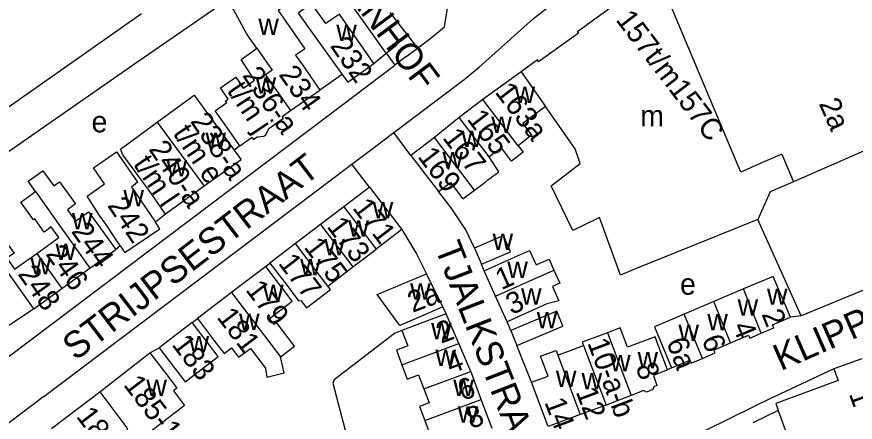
# Model space of a CAD drawing. Extents: x 159261 to 160849, y 382514 to 384534.
# Drawn here: x 159434.5 to 159592.3, y 383430.4 to 383506.6 of the extents above; entities that cross this region are included whole.
import ezdxf

# ---------------------------------------------------------------- set-up
doc = ezdxf.new("R2010")
doc.units = 0
for name, color, linetype in [('BLT_Basislijn', 7, 'Continuous'), ('BLT_Bebouwing', 7, 'Continuous'), ('BLT_Centroide', 7, 'Continuous'), ('BLT_Huisnummer', 7, 'Continuous'), ('BLT_Huisnummer_ tussenligend', 7, 'Continuous'), ('BLT_Huisnummer_reeks', 7, 'Continuous'), ('BLT_Onderverdeling_panden', 7, 'Continuous'), ('BLT_Straatnaam', 7, 'Continuous'), ('BLT_Vlakafsluiter', 7, 'Continuous')]:
    doc.layers.add(name, color=color, linetype=linetype)

msp = doc.modelspace()

# ---------------------------------------------------------------- linework, layer by layer
at = {"layer": 'BLT_Basislijn'}
for p, q in [((159504.04, 383499.76), (159490.29, 383519.05)), ((159474.26, 383509.88), (159456.51, 383497.57)), ((159504.7, 383507.46), (159509.94, 383500.74)), ((159504.04, 383499.76), (159506.03, 383501.34)), ((159501.7, 383497.84), (159504.04, 383499.76)), ((159504.04, 383499.76), (159505.65, 383497.5)), ((159456.51, 383497.57), (159422.23, 383473.79)), ((159495.77, 383495.76), (159491.55, 383492.84)), ((159508.68, 383480.51), (159505.5, 383484.86)), ((159476.46, 383482.36), (159475.45, 383481.51)), ((159500.88, 383474.55), (159497.57, 383478.88)), ((159462.52, 383469.49), (159460.59, 383467.98)), ((159582.13, 383450.36), (159573.98, 383468.47)), ((159454, 383463.51), (159453.14, 383462.88)), ((159481.37, 383459.66), (159482.14, 383460.29)), ((159522.47, 383458.85), (159521.96, 383460.08)), ((159515.33, 383450.76), (159514.66, 383452.08)), ((159467.55, 383449.1), (159468.52, 383449.86)), ((159582.13, 383450.36), (159580.11, 383450.13)), ((159527.46, 383447.6), (159526.77, 383449.24)), ((159459.55, 383443.43), (159461.32, 383444.35)), ((159531.39, 383437.88), (159528.62, 383444.82)), ((159557.75, 383440.56), (159556.95, 383440.24)), ((159577.81, 383432.59), (159573.03, 383430.24))]:
    msp.add_line(p, q, dxfattribs=at)
for points in [[(159505.5, 383484.86), (159518.69, 383494.81), (159521.53, 383497.18), (159531.74, 383506.29), (159551.48, 383521.62), (159560.64, 383527.81), (159570.61, 383533.89), (159574.46, 383535.84), (159576.68, 383536.75), (159577.57, 383534.45), (159623.26, 383552.14), (159622.41, 383554.33), (159627.34, 383556.21), (159628.86, 383556.59), (159630.56, 383556.59), (159632, 383556.22), (159633.7, 383555.46), (159634.34, 383554.89), (159634.81, 383554.05)], [(159509.94, 383500.74), (159512.47, 383502.65), (159515, 383504.75), (159515.83, 383509.77), (159535.19, 383525.66), (159540.37, 383529.61), (159549.52, 383536.01), (159553.92, 383535.43), (159554.55, 383535.97), (159555.34, 383537.11), (159555.78, 383538.15), (159555.95, 383539.22), (159555.84, 383540.38), (159555.5, 383541.77)], [(159422.23, 383473.79), (159418.8, 383478.76), (159418.9, 383479.86), (159458, 383507.23)], [(159507.74, 383499.08), (159509.94, 383500.74)], [(159430.35, 383440.97), (159433.6, 383443.17), (159492.79, 383487.8), (159505.65, 383497.5)], [(159497.57, 383478.88), (159501.56, 383481.89)], [(159439.63, 383435.19), (159497.57, 383478.88)], [(159520.66, 383463.11), (159519.02, 383466.54), (159516.28, 383470.69), (159513.89, 383473.73)], [(159628.07, 383468.9), (159621.56, 383466.62), (159582.13, 383450.36)], [(159506.95, 383466.59), (159509.72, 383462.03), (159511.6, 383458.28)], [(159437.72, 383451.68), (159432.56, 383448.25), (159426.76, 383444.96), (159420.88, 383442.27), (159412.54, 383439.19), (159400.66, 383435.2)], [(159507, 383447.64), (159505.57, 383447.05), (159494.22, 383438.3), (159494.02, 383437.69), (159498.26, 383421.44)], [(159588.26, 383440.37), (159576.24, 383434.73), (159573.02, 383433.17), (159555.06, 383424.37), (159552.31, 383421.68), (159551.85, 383417.92), (159572.25, 383356.82)], [(159439.63, 383435.19), (159399.52, 383404.89)]]:
    msp.add_lwpolyline(points, dxfattribs=at)
at = {"layer": 'BLT_Bebouwing'}
for p, q in [((159543.32, 383506.24), (159551.33, 383512.07)), ((159532.72, 383498.22), (159540.25, 383503.62)), ((159529.42, 383496.29), (159522.24, 383491.08)), ((159486.05, 383488.98), (159491.55, 383492.84)), ((159522.24, 383491.08), (159517.79, 383487.68)), ((159517.79, 383487.68), (159513.14, 383483.89)), ((159603.64, 383485.66), (159580.7, 383475.6)), ((159513.14, 383483.89), (159508.68, 383480.51)), ((159508.68, 383480.51), (159513.89, 383473.73)), ((159469.79, 383474.74), (159462.52, 383469.49)), ((159500.88, 383474.55), (159506.95, 383466.59)), ((159496.05, 383470.9), (159491.69, 383467.57)), ((159491.69, 383467.57), (159486.96, 383463.96)), ((159486.96, 383463.96), (159482.14, 383460.29)), ((159448.29, 383459.36), (159453.14, 383462.88)), ((159520.66, 383463.11), (159521.96, 383460.08)), ((159442.98, 383455.5), (159448.29, 383459.36)), ((159481.37, 383459.66), (159474.95, 383454.76)), ((159493.05, 383455.98), (159497.77, 383459.59)), ((159514.66, 383452.08), (159511.6, 383458.28)), ((159524.62, 383454.05), (159522.47, 383458.85)), ((159437.72, 383451.68), (159442.98, 383455.5)), ((159474.95, 383454.76), (159468.52, 383449.86)), ((159571.26, 383455.42), (159565.68, 383453.04)), ((159526.77, 383449.24), (159524.62, 383454.05)), ((159565.68, 383453.04), (159560.11, 383450.66)), ((159517.69, 383445.18), (159515.33, 383450.76)), ((159467.55, 383449.1), (159461.32, 383444.35)), ((159527.46, 383447.6), (159528.62, 383444.82)), ((159519.93, 383439.92), (159517.69, 383445.18)), ((159450.14, 383436.07), (159459.55, 383443.43)), ((159536.34, 383442.94), (159541.18, 383444.76)), ((159593.52, 383442.31), (159588.26, 383440.37)), ((159441.02, 383429.18), (159450.14, 383436.07)), ((159523.97, 383429.19), (159521.93, 383434.65)), ((159550.15, 383435.39), (159545.4, 383433.59)), ((159577.34, 383433.88), (159577.81, 383432.59)), ((159545.4, 383433.59), (159540.54, 383431.78)), ((159577.81, 383432.59), (159584.04, 383415.32))]:
    msp.add_line(p, q, dxfattribs=at)
for points in [[(159479.51, 383514.59), (159479.76, 383514.15), (159482.73, 383516.23), (159486.55, 383508.99), (159485.26, 383508.1), (159484.96, 383508.66), (159483.73, 383507.8), (159488.7, 383500.6), (159487.86, 383500), (159486.99, 383499.4), (159488.7, 383496.95), (159491.55, 383492.84)], [(159479.71, 383500.7), (159478.13, 383502.94), (159477.71, 383503.62), (159475.33, 383507.97), (159474.26, 383509.88)], [(159501.7, 383497.84), (159495.23, 383507.14), (159492.65, 383505.34), (159489.95, 383509.11), (159487.48, 383507.34), (159495.77, 383495.76)], [(159540.25, 383503.62), (159540.06, 383503.89), (159543.32, 383506.24)], [(159476.46, 383482.36), (159473.59, 383486.46), (159471.84, 383488.96), (159474.02, 383490.49), (159473.81, 383490.8), (159474.31, 383491.16), (159472.86, 383493.24), (159475.73, 383495.25), (159477.15, 383493.23), (159479.24, 383494.69), (159476.72, 383498.61), (159478.71, 383500), (159479.71, 383500.7)], [(159495.77, 383495.76), (159496.81, 383494.3), (159501.7, 383497.84)], [(159532.72, 383498.22), (159532.52, 383498.5), (159529.42, 383496.29)], [(159460.94, 383486.78), (159467.89, 383491.89), (159475.45, 383481.51)], [(159533.99, 383489.77), (159529.75, 383486.53), (159531.4, 383484.37), (159528.88, 383482.38)], [(159540.55, 383479.05), (159539.58, 383481.78), (159533.99, 383489.77)], [(159476.46, 383482.36), (159478.79, 383484), (159479.09, 383483.57), (159479.74, 383484.03), (159481.02, 383484.15), (159481.4, 383484.42), (159481.95, 383485.61), (159484.71, 383487.54), (159484.48, 383487.87), (159486.05, 383488.98)], [(159462.52, 383469.49), (159459.72, 383473.52), (159454.46, 383480.69), (159454.06, 383481.72), (159460.94, 383486.78)], [(159454, 383463.51), (159451.25, 383467.6), (159450.1, 383469.25), (159447.74, 383472.89), (159451.03, 383475.22), (159448.95, 383478.23), (159453.26, 383481.23), (159457.22, 383475.5), (159456.13, 383474.58), (159456.76, 383473.67), (159457.8, 383472.13), (159460.59, 383467.98)], [(159475.45, 383481.51), (159476.72, 383479.74), (159469.79, 383474.74)], [(159528.88, 383482.38), (159529.82, 383481.14), (159527.64, 383479.47), (159525.71, 383482), (159523.44, 383480.27)], [(159520.67, 383474.03), (159522.57, 383475.48), (159523.17, 383475.94), (159525.2, 383477.49), (159523.44, 383480.27)], [(159543.78, 383468.66), (159539.18, 383466.45), (159535.05, 383474.81), (159540.55, 383479.05)], [(159438.06, 383473.75), (159436.67, 383475.71), (159439.44, 383477.68), (159441.47, 383474.83), (159442.57, 383475.61), (159445.56, 383471.41), (159444.05, 383470.34), (159445.56, 383468.21), (159448.01, 383469.94), (159450.2, 383466.93), (159453.14, 383462.88)], [(159513.89, 383473.73), (159516.14, 383475.44), (159518.48, 383472.36), (159520.67, 383474.03)], [(159580.7, 383475.6), (159576.31, 383473.67), (159573.98, 383468.47)], [(159438.27, 383462.12), (159442.43, 383465.08), (159441, 383467.09), (159439.66, 383466.14), (159437.93, 383468.59), (159437.68, 383468.42), (159435.29, 383471.78), (159438.06, 383473.75)], [(159500.88, 383474.55), (159499.99, 383473.9), (159496.05, 383470.9)], [(159550.64, 383459.07), (159548.1, 383458), (159544.16, 383468.84), (159543.78, 383468.66)], [(159454, 383463.51), (159454.82, 383462.29), (159461.43, 383466.73), (159460.59, 383467.98)], [(159573.98, 383468.47), (159550.64, 383459.07)], [(159506.95, 383466.59), (159502.98, 383463.56), (159502.14, 383462.92)], [(159521.96, 383460.08), (159527.43, 383462.44), (159526.13, 383465.46), (159520.66, 383463.11)], [(159429.76, 383462.87), (159432.24, 383464.63), (159434.01, 383462.15), (159432.67, 383461.2), (159434.11, 383459.17), (159438.27, 383462.12)], [(159437.72, 383451.68), (159434.82, 383455.75), (159429.76, 383462.87)], [(159497.77, 383459.59), (159500, 383461.29), (159502.14, 383462.92)], [(159522.47, 383458.85), (159527.04, 383460.89), (159531.03, 383462.68), (159532.25, 383459.94), (159534.67, 383461.02), (159535.59, 383458.96)], [(159484.17, 383442.67), (159486.77, 383444.66), (159483.38, 383449.1), (159482.93, 383448.76), (159482.09, 383449.87), (159486.36, 383453.13), (159484.41, 383455.69), (159481.37, 383459.66)], [(159482.14, 383460.29), (159485.18, 383456.31), (159487.56, 383453.19), (159487.97, 383453.24), (159489.01, 383451.89), (159493.54, 383455.34), (159493.05, 383455.98)], [(159514.66, 383452.08), (159510.09, 383450.07), (159506.63, 383448.54), (159502.36, 383454.38), (159506.99, 383456.33), (159511.6, 383458.28)], [(159535.59, 383458.96), (159536.69, 383456.51), (159535.32, 383455.87), (159536.51, 383453.22)], [(159580.11, 383450.13), (159576.84, 383457.8), (159571.26, 383455.42)], [(159536.51, 383453.22), (159534.29, 383452.61), (159526.77, 383449.24)], [(159528.62, 383444.82), (159537.28, 383448.44), (159536.12, 383451.22), (159527.46, 383447.6)], [(159468.52, 383449.86), (159471.56, 383445.88), (159473.55, 383443.28), (159474.92, 383444.32), (159476.26, 383442.57), (159478.47, 383444.25), (159481.33, 383440.5), (159481.55, 383438.84), (159484.86, 383439.64), (159484.17, 383442.67)], [(159515.33, 383450.76), (159510.64, 383449.01), (159507, 383447.64)], [(159560.11, 383450.66), (159554.53, 383448.28), (159557.75, 383440.56)], [(159574.62, 383447.11), (159576.96, 383448.12), (159576.72, 383448.67), (159580.11, 383450.13)], [(159461.32, 383444.35), (159464.35, 383440.38), (159466.21, 383437.95), (159472.41, 383442.73), (159470.58, 383445.12), (159467.55, 383449.1)], [(159556.95, 383440.24), (159555.23, 383444.83), (159554.62, 383446.43), (159549.45, 383444.49), (159548.09, 383448.1), (159545.7, 383447.2)], [(159507, 383447.64), (159508.1, 383444.71), (159505.97, 383443.91), (159506.99, 383441.18)], [(159545.7, 383447.2), (159540.94, 383445.41), (159541.18, 383444.76)], [(159568.84, 383445.28), (159572.22, 383446.73), (159572.46, 383446.18), (159574.62, 383447.11)], [(159563.55, 383442.36), (159565.94, 383443.39), (159565.7, 383443.94), (159568.84, 383445.28)], [(159459.55, 383443.43), (159462.79, 383439.18), (159464.65, 383436.75), (159463.99, 383436.24), (159466.09, 383433.5), (159459.78, 383428.69), (159463.62, 383423.66), (159464.67, 383420.47), (159459.02, 383416.09)], [(159531.39, 383437.88), (159534.49, 383439.05), (159533.09, 383442.78), (159535.99, 383443.88), (159536.34, 383442.94)], [(159557.75, 383440.56), (159561.19, 383442), (159561.43, 383441.45), (159563.55, 383442.36)], [(159506.99, 383441.18), (159508.01, 383438.45), (159510.14, 383439.24), (159511.12, 383436.62)], [(159556.95, 383440.24), (159554.31, 383439.15), (159554.96, 383437.24), (159554.41, 383437.04), (159554.22, 383436.5), (159552.99, 383436.02), (159552.55, 383436.23), (159552.52, 383436.32), (159550.15, 383435.39)], [(159588.26, 383440.37), (159589.06, 383438.2), (159577.34, 383433.88)], [(159521.93, 383434.65), (159520.12, 383439.46), (159519.93, 383439.92)], [(159540.54, 383431.78), (159534.53, 383429.52), (159531.39, 383437.88)], [(159511.12, 383436.62), (159512.1, 383434.01), (159510.3, 383433.33), (159511.29, 383430.67)], [(159511.29, 383430.67), (159512.29, 383428.01), (159514.18, 383428.71), (159515.23, 383425.91)]]:
    msp.add_lwpolyline(points, dxfattribs=at)
at = {"layer": 'BLT_Onderverdeling_panden'}
for p, q in [((159570.76, 383477.42), (159557.63, 383508.54)), ((159529.42, 383496.29), (159533.99, 383489.77)), ((159528.88, 383482.38), (159522.24, 383491.08)), ((159523.44, 383480.27), (159517.79, 383487.68)), ((159460.94, 383486.78), (159469.79, 383474.74)), ((159520.67, 383474.03), (159513.14, 383483.89)), ((159578.5, 383480.78), (159574.39, 383479.02)), ((159574.39, 383479.02), (159570.76, 383477.42)), ((159438.06, 383473.75), (159448.29, 383459.36)), ((159496.05, 383470.9), (159502.14, 383462.92)), ((159491.69, 383467.57), (159497.77, 383459.59)), ((159493.05, 383455.98), (159486.96, 383463.96)), ((159438.27, 383462.12), (159442.98, 383455.5)), ((159524.62, 383454.05), (159535.59, 383458.96)), ((159474.95, 383454.76), (159484.17, 383442.67)), ((159574.62, 383447.11), (159571.26, 383455.42)), ((159568.84, 383445.28), (159565.68, 383453.04)), ((159563.55, 383442.36), (159560.11, 383450.66)), ((159545.7, 383447.2), (159550.15, 383435.39)), ((159506.99, 383441.18), (159517.69, 383445.18)), ((159541.18, 383444.76), (159545.4, 383433.59)), ((159536.34, 383442.94), (159540.54, 383431.78)), ((159511.12, 383436.62), (159519.93, 383439.92)), ((159511.29, 383430.67), (159521.93, 383434.65))]:
    msp.add_line(p, q, dxfattribs=at)
for points in [[(159479.71, 383500.7), (159482.6, 383496.61), (159481.3, 383495.7), (159486.05, 383488.98)], [(159578.5, 383480.78), (159580.7, 383475.6)], [(159450.14, 383436.07), (159455.21, 383429.3), (159457.5, 383421.36)]]:
    msp.add_lwpolyline(points, dxfattribs=at)
at = {"layer": 'BLT_Vlakafsluiter'}
for p, q in [((159507.74, 383499.08), (159505.65, 383497.5)), ((159501.56, 383481.89), (159505.5, 383484.86))]:
    msp.add_line(p, q, dxfattribs=at)

# ---------------------------------------------------------------- texts
at = {"layer": 'BLT_Centroide'}
for s, p in [('w', (159479.97, 383503.2)), ('w', (159494.64, 383502.09)), ('w', (159479.47, 383492.19)), ('w', (159528.2, 383490.44)), ('m', (159551.84, 383486)), ('e', (159448.59, 383484.89)), ('w', (159523.81, 383484.78)), ('w', (159470.02, 383481.78)), ('w', (159518.19, 383482.12)), ('w', (159462.7, 383476.59)), ('w', (159514.62, 383478.11)), ('w', (159454.59, 383470.97)), ('w', (159501.5, 383468.73)), ('w', (159444.91, 383466.62)), ('w', (159496.92, 383465.25)), ('w', (159524.05, 383462.78)), ('w', (159441.8, 383460.89)), ('w', (159492.38, 383461.78)), ('w', (159437.1, 383458.16)), ('w', (159487.84, 383458.02)), ('w', (159526.83, 383457.46)), ('w', (159480.86, 383453.14)), ('w', (159508.54, 383453.41)), ('e', (159559.33, 383454.35)), ('w', (159529.41, 383452.49)), ('w', (159575.69, 383452.44)), ('w', (159570.16, 383450.39)), ('w', (159476.34, 383447.69)), ('w', (159532.37, 383448.03)), ('w', (159564.47, 383447.64)), ('w', (159512.49, 383445.97)), ('w', (159559.03, 383445.64)), ('w', (159466.86, 383443.53)), ('w', (159513.3, 383440.91)), ('w', (159551.33, 383440.52)), ('w', (159546.17, 383439.94)), ('w', (159535.97, 383436.97)), ('w', (159540.8, 383436.52)), ('w', (159458.91, 383435.27)), ('w', (159516.66, 383435.28)), ('w', (159517.5, 383430.28))]:
    msp.add_text(s, height=4, dxfattribs=at).set_placement(p)
at = {"layer": 'BLT_Huisnummer'}
for s, rotation, p in [('232', 304.7611, (159493.37, 383501.17)), ('234', 305.0568, (159483.7, 383495.77)), ('163a', 307.3356, (159524.36, 383492.44)), ('165', 307.3374, (159519.09, 383487.35)), ('169', 307.3375, (159509.82, 383480.3)), ('242', 303.9086, (159451.47, 383471.11)), ('171', 307.3437, (159497.56, 383470.66)), ('244', 305.4049, (159444.64, 383466.25)), ('177', 307.3443, (159483.58, 383460.25)), ('248', 305.4604, (159434.59, 383458.22)), ('1', 24.1149, (159525.71, 383455.17)), ('2a', 20.5265, (159508.98, 383450.92)), ('3', 22.6635, (159527.59, 383450.52)), ('2', 292.0204, (159574.62, 383450.7)), ('2', 20.5265, (159514.36, 383445.11)), ('183', 307.3443, (159463.56, 383444.94)), ('6', 292.0204, (159563.34, 383445.92)), ('6a', 290.6311, (159556.71, 383445.47)), ('8', 290.6255, (159550.91, 383440.74)), ('6', 20.5277, (159518.39, 383434.29)), ('1', 290.2798, (159591.06, 383435.7)), ('14', 290.6296, (159533.77, 383434.14))]:
    msp.add_text(s, height=4, rotation=rotation, dxfattribs=at).set_placement(p)
at = {"layer": 'BLT_Huisnummer_ tussenligend'}
for s, rotation, p in [('167', 307.3374, (159514.51, 383483.85)), ('173', 307.3437, (159492.73, 383467.15)), ('175', 307.3437, (159488.41, 383463.27)), ('246', 305.4604, (159439.83, 383462)), ('179', 307.3443, (159477.44, 383455.24)), ('181', 307.3443, (159472.02, 383450.09)), ('4', 292.0204, (159569.13, 383448.42)), ('4', 20.5265, (159516.16, 383439.41)), ('12', 290.6255, (159539.66, 383436.1)), ('8', 20.5277, (159519.99, 383429.05))]:
    msp.add_text(s, height=4, rotation=rotation, dxfattribs=at).set_placement(p)
at = {"layer": 'BLT_Huisnummer_reeks'}
for s, rotation, p in [('157t/m157C', 307.3376, (159547.1, 383506.04)), ('236-a', 303.9086, (159476.86, 383495.6)), ('t/m j', 303.9086, (159473.94, 383492.78)), ('2a', 293.9529, (159585.39, 383490.3)), ('238-a', 303.9086, (159467.06, 383486.98)), ('t/m e', 303.9086, (159463.77, 383484.71)), ('240-a', 303.9086, (159459.24, 383481.72)), ('t/m l', 303.9086, (159456.3, 383478.93)), ('10-a-b', 290.6255, (159541.83, 383445.33)), ('185-185a', 307.3243, (159454.46, 383437.38)), ('187-189', 307.3411, (159445.55, 383431.43))]:
    msp.add_text(s, height=4, rotation=rotation, dxfattribs=at).set_placement(p)
at = {"layer": 'BLT_Straatnaam'}
for s, rotation, p in [('SIERMANHOF', 306.7661, (159483.68, 383528)), ('STRIJPSESTRAAT', 37.4383, (159445.57, 383441.79)), ('KLIPPERSTRAAT', 23.6748, (159578.28, 383439.94)), ('TJALKSTRAAT', 291.3205, (159513.12, 383463.2))]:
    msp.add_text(s, height=5, rotation=rotation, dxfattribs=at).set_placement(p)

doc.saveas('drawing.dxf')
